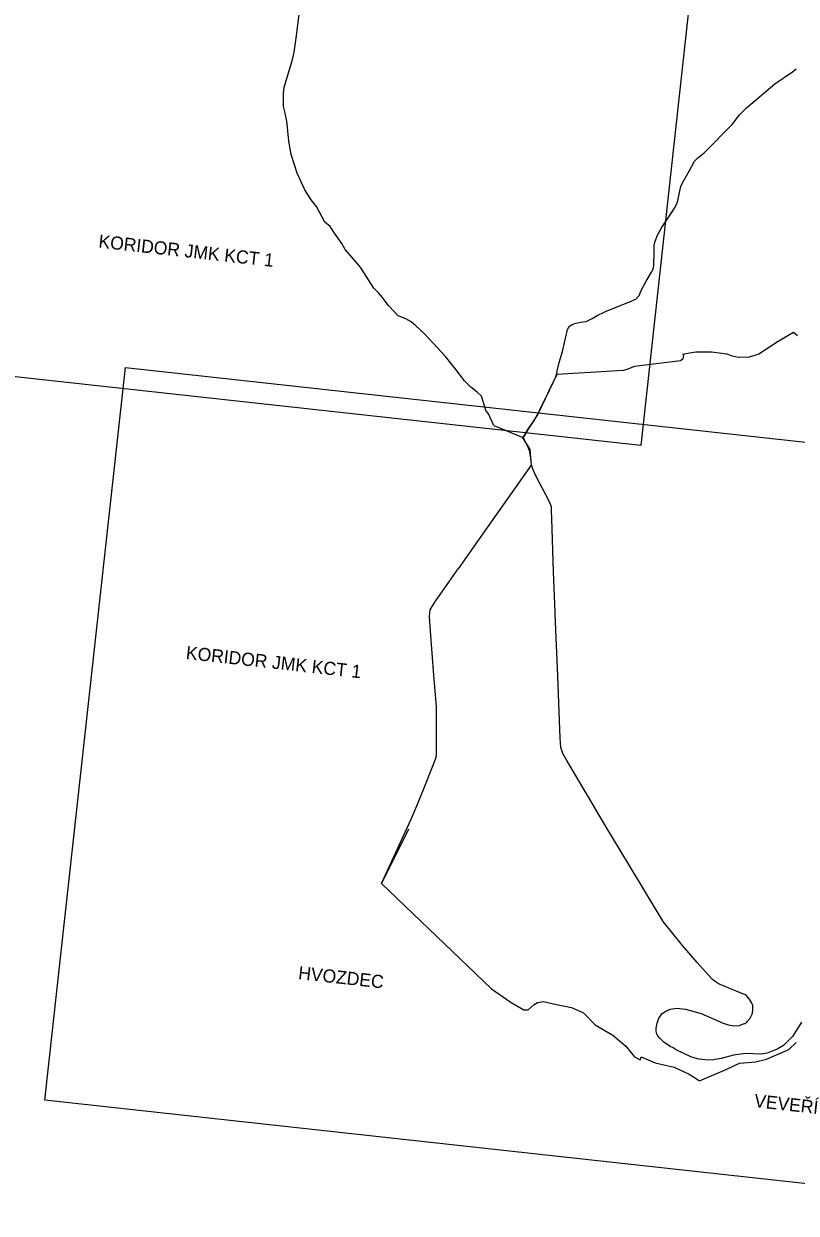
# Model space of a CAD drawing. Extents: x -678204 to -526855, y -1228851 to -1110393.
# Drawn here: x -611868 to -608331, y -1154035 to -1148586 of the extents above; entities that cross this region are included whole.
import ezdxf

# ---------------------------------------------------------------- set-up
doc = ezdxf.new("R2010")
doc.units = 0
for name, color, linetype in [('00_n_cyklo popisy detaily', 7, 'Continuous'), ('00_n_cyklo provereni rekreacni hlavni', 7, 'Continuous'), ('00_n_cyklo provereni vedlejsi', 7, 'Continuous'), ('00_n_cyklo prujezdne rekreacni hlavni', 7, 'Continuous'), ('00_n_cyklo prujezdne rekreacni vedlejsi', 7, 'Continuous'), ('00_n_cyklo trasovani rekreacni hlavni', 7, 'Continuous'), ('00_n_cyklo trasovani rekreacni vedlejsi', 7, 'Continuous'), ('_HELP', 7, 'Continuous'), ('trasy_0001', 7, 'Continuous')]:
    doc.layers.add(name, color=color, linetype=linetype)

msp = doc.modelspace()

# ---------------------------------------------------------------- linework, layer by layer
at = {"layer": '00_n_cyklo provereni rekreacni hlavni'}
msp.add_lwpolyline([(-610229.4, -1152524.2), (-609726.1, -1153007), (-609635.8, -1153070.5), (-609578.3, -1153104.1), (-609558.5, -1153103), (-609530.7, -1153078.7), (-609515.6, -1153070.6), (-609488.7, -1153064.8), (-609429.1, -1153079), (-609360.6, -1153092), (-609305.4, -1153116.6), (-609251.3, -1153171.7), (-609170.1, -1153218.9), (-609111.3, -1153270.2), (-609071.8, -1153318.3), (-609046.1, -1153333.1), (-609041.3, -1153319.5), (-608976.5, -1153346.2), (-608890.1, -1153365.6), (-608821.5, -1153398.3), (-608797, -1153414.1), (-608774.6, -1153428.6), (-608648.6, -1153375.7), (-608590.9, -1153348.1), (-608517, -1153342), (-608466.4, -1153329), (-608364.2, -1153284.5), (-608331.3, -1153253.1)], dxfattribs=at)
at = {"layer": '00_n_cyklo provereni vedlejsi'}
msp.add_lwpolyline([(-608324.7, -1150015.4), (-608342.7, -1150000.3), (-608413.9, -1150041.7), (-608502.3, -1150099.8), (-608546.4, -1150113.5), (-608594.6, -1150114.8), (-608622.3, -1150108.5), (-608648.7, -1150100.1), (-608718.2, -1150091.1), (-608790.3, -1150090.8), (-608835.9, -1150097.8), (-608851.5, -1150100.5)], dxfattribs=at)
at = {"layer": '00_n_cyklo prujezdne rekreacni hlavni'}
for points in [[(-609716.2, -1150426.9), (-609740.5, -1150373.6), (-609751.7, -1150358.4), (-609762.3, -1150321.4), (-609772, -1150291.4), (-609792.3, -1150273.7), (-609820.9, -1150250.8), (-609849.9, -1150221.8), (-609894.4, -1150164.2), (-609936.9, -1150111), (-609972, -1150072.7), (-610034.8, -1150005), (-610073.4, -1149969.9), (-610095, -1149951.5), (-610119.1, -1149937.4), (-610154.3, -1149924.8), (-610198.1, -1149876.8), (-610226.4, -1149838.5), (-610242.5, -1149820.7), (-610265, -1149796.6), (-610324.3, -1149704.4), (-610333.6, -1149691.6), (-610396.1, -1149620.4), (-610411.6, -1149592.7), (-610445.4, -1149545.9), (-610464.7, -1149514.1), (-610489.2, -1149494.7), (-610528.5, -1149422.9), (-610551.7, -1149393.2), (-610580.6, -1149347.2), (-610616.1, -1149270.8), (-610644.4, -1149184.8), (-610654.4, -1149124.3), (-610658.3, -1149076.6), (-610663.1, -1149032.4), (-610670.8, -1148995.1), (-610678.2, -1148965.1), (-610679.2, -1148904.9), (-610675.3, -1148877.2), (-610639.2, -1148755.4), (-610629.6, -1148715.8), (-610619.9, -1148642), (-610607.7, -1148541.5)], [(-609716.2, -1150426.9), (-609585.2, -1150479.7), (-609551.1, -1150537), (-609544.8, -1150608.8), (-609728.4, -1150867.5), (-609878.9, -1151083.4)], [(-610229.4, -1152524.2), (-610094.5, -1152230.5), (-610064.4, -1152158.2), (-610026.3, -1152063), (-609980.5, -1151947.7), (-609977.7, -1151927.6), (-609978.1, -1151748.4), (-609978.5, -1151715), (-609990.5, -1151570.4), (-610006.2, -1151368.3), (-610010.2, -1151300.8), (-610006.6, -1151270.6), (-609986.5, -1151236.5), (-609878.9, -1151083.4)], [(-610106.5, -1152276.3), (-610229.4, -1152524.2)]]:
    msp.add_lwpolyline(points, dxfattribs=at)
at = {"layer": '00_n_cyklo prujezdne rekreacni vedlejsi'}
msp.add_lwpolyline([(-608847.3, -1150101.4), (-608849.6, -1150121.9), (-608860.2, -1150129.5), (-609070.9, -1150156.6), (-609106.2, -1150170.3), (-609121.9, -1150174), (-609426.8, -1150193), (-609516, -1150378.2), (-609556.3, -1150440.5), (-609581.7, -1150482)], dxfattribs=at)
at = {"layer": '00_n_cyklo trasovani rekreacni hlavni'}
for points in [[(-609716.2, -1150426.9), (-609740.5, -1150373.6), (-609751.7, -1150358.4), (-609762.3, -1150321.4), (-609772, -1150291.4), (-609792.3, -1150273.7), (-609820.9, -1150250.8), (-609849.9, -1150221.8), (-609894.4, -1150164.2), (-609936.9, -1150111), (-609972, -1150072.7), (-610034.8, -1150005), (-610073.4, -1149969.9), (-610095, -1149951.5), (-610119.1, -1149937.4), (-610154.3, -1149924.8), (-610198.1, -1149876.8), (-610226.4, -1149838.5), (-610242.5, -1149820.7), (-610265, -1149796.6), (-610324.3, -1149704.4), (-610333.6, -1149691.6), (-610396.1, -1149620.4), (-610411.6, -1149592.7), (-610445.4, -1149545.9), (-610464.7, -1149514.1), (-610489.2, -1149494.7), (-610528.5, -1149422.9), (-610551.7, -1149393.2), (-610580.6, -1149347.2), (-610616.1, -1149270.8), (-610644.4, -1149184.8), (-610654.4, -1149124.3), (-610658.3, -1149076.6), (-610663.1, -1149032.4), (-610670.8, -1148995.1), (-610678.2, -1148965.1), (-610679.2, -1148904.9), (-610675.3, -1148877.2), (-610639.2, -1148755.4), (-610629.6, -1148715.8), (-610619.9, -1148642), (-610607.7, -1148541.5)], [(-609716.2, -1150426.9), (-609585.2, -1150479.7), (-609551.1, -1150537), (-609544.8, -1150608.8), (-609728.4, -1150867.5), (-609878.9, -1151083.4)], [(-610229.4, -1152524.2), (-610094.5, -1152230.5), (-610064.4, -1152158.2), (-610026.3, -1152063), (-609980.5, -1151947.7), (-609977.7, -1151927.6), (-609978.1, -1151748.4), (-609978.5, -1151715), (-609990.5, -1151570.4), (-610006.2, -1151368.3), (-610010.2, -1151300.8), (-610006.6, -1151270.6), (-609986.5, -1151236.5), (-609878.9, -1151083.4)], [(-610106.5, -1152276.3), (-610229.4, -1152524.2)], [(-610229.4, -1152524.2), (-609726.1, -1153007), (-609635.8, -1153070.5), (-609578.3, -1153104.1), (-609558.5, -1153103), (-609530.7, -1153078.7), (-609515.6, -1153070.6), (-609488.7, -1153064.8), (-609429.1, -1153079), (-609360.6, -1153092), (-609305.4, -1153116.6), (-609251.3, -1153171.7), (-609170.1, -1153218.9), (-609111.3, -1153270.2), (-609071.8, -1153318.3), (-609046.1, -1153333.1), (-609041.3, -1153319.5), (-608976.5, -1153346.2), (-608890.1, -1153365.6), (-608821.5, -1153398.3), (-608797, -1153414.1), (-608774.6, -1153428.6), (-608648.6, -1153375.7), (-608590.9, -1153348.1), (-608517, -1153342), (-608466.4, -1153329), (-608364.2, -1153284.5), (-608331.3, -1153253.1)]]:
    msp.add_lwpolyline(points, dxfattribs=at)
at = {"layer": '00_n_cyklo trasovani rekreacni vedlejsi'}
for points in [[(-608324.7, -1150015.4), (-608342.7, -1150000.3), (-608413.9, -1150041.7), (-608502.3, -1150099.8), (-608546.4, -1150113.5), (-608594.6, -1150114.8), (-608622.3, -1150108.5), (-608648.7, -1150100.1), (-608718.2, -1150091.1), (-608790.3, -1150090.8), (-608835.9, -1150097.8), (-608851.5, -1150100.5)], [(-608847.3, -1150101.4), (-608849.6, -1150121.9), (-608860.2, -1150129.5), (-609070.9, -1150156.6), (-609106.2, -1150170.3), (-609121.9, -1150174), (-609426.8, -1150193), (-609516, -1150378.2), (-609556.3, -1150440.5), (-609581.7, -1150482)]]:
    msp.add_lwpolyline(points, dxfattribs=at)
at = {"layer": '_HELP'}
for points in [[(-613388.8, -1146642.2), (-608674.3, -1147159.9), (-609043, -1150517.4), (-613757.5, -1149999.7)], [(-611402.9, -1150160), (-606688.3, -1150677.7), (-607057, -1154035.2), (-611771.6, -1153517.5)]]:
    msp.add_lwpolyline(points, close=True, dxfattribs=at)
at = {"layer": 'trasy_0001'}
msp.add_lwpolyline([(-608307, -1153160.2), (-608348.4, -1153225.9), (-608388.7, -1153267.4), (-608418.9, -1153283), (-608464.2, -1153302.5), (-608488.2, -1153306.6), (-608529.8, -1153304.4), (-608547.5, -1153302.9), (-608573.9, -1153304.8), (-608617.9, -1153311.7), (-608674.1, -1153326.2), (-608702.7, -1153331.2), (-608715.8, -1153333.5), (-608748, -1153333), (-608774.8, -1153328.8), (-608783.2, -1153327.5), (-608813.8, -1153319.2), (-608880.9, -1153286.7), (-608894.1, -1153278.2), (-608907.5, -1153271.4), (-608937.4, -1153251.1), (-608955.9, -1153233.9), (-608965.9, -1153220.8), (-608970.2, -1153209.3), (-608972.4, -1153200.1), (-608972, -1153187.5), (-608968.3, -1153164.8), (-608959.5, -1153141.7), (-608944.3, -1153119.9), (-608924.9, -1153108.3), (-608907.2, -1153100), (-608879, -1153095.8), (-608837.3, -1153100.9), (-608766.5, -1153120.9), (-608665.7, -1153164.5), (-608640.5, -1153172.7), (-608616.9, -1153177.3), (-608591.6, -1153175), (-608572.5, -1153167.3), (-608567, -1153165.5), (-608557.6, -1153159.4), (-608553.7, -1153155.8), (-608542.2, -1153141.4), (-608538.2, -1153135.5), (-608533.4, -1153123.8), (-608531.7, -1153117), (-608530, -1153103.3), (-608529.6, -1153085.4), (-608529.6, -1153083.4), (-608536, -1153070.6), (-608540.1, -1153062.3), (-608545.5, -1153054.1), (-608562, -1153035.4), (-608579.5, -1153028.2), (-608601.8, -1153019.1), (-608638.8, -1153003.9), (-608658.8, -1152995.7), (-608683.1, -1152985.6), (-608702.1, -1152973.1), (-608714.4, -1152963.9), (-608732.1, -1152944.5), (-608772.1, -1152900.6), (-608784.7, -1152886.8), (-608851.2, -1152809.2), (-608940.6, -1152699), (-609097.5, -1152437), (-609202.5, -1152263.4), (-609263.3, -1152160.1), (-609381.3, -1151961.6), (-609399.4, -1151929.2), (-609408.7, -1151901.3), (-609411.9, -1151859.1), (-609422.4, -1151574.1), (-609434.5, -1151291.3), (-609435.1, -1151282.5), (-609441.1, -1151133.1), (-609442, -1151095.6), (-609450.1, -1150853.2), (-609451, -1150819.4), (-609451.5, -1150799.2), (-609460.3, -1150775.7), (-609524.9, -1150653.3), (-609538.7, -1150621.9), (-609543.4, -1150606.2), (-609546.6, -1150577.5), (-609550.4, -1150547.8), (-609556.8, -1150530.7), (-609565.1, -1150513.6), (-609581.7, -1150482), (-609556.3, -1150440.5), (-609532.4, -1150406.8), (-609516, -1150378.2), (-609499, -1150340.3), (-609467.6, -1150276.1), (-609464, -1150269.2), (-609432.6, -1150206.8), (-609428.4, -1150195), (-609425.1, -1150177.4), (-609416, -1150137.9), (-609400.8, -1150087.4), (-609378.2, -1149987.3), (-609370.3, -1149973.6), (-609357.5, -1149963.6), (-609340.3, -1149957.5), (-609308.5, -1149951.7), (-609292.2, -1149949.6), (-609289.1, -1149948.6), (-609264.7, -1149936.4), (-609242.7, -1149923.1), (-609204.6, -1149904), (-609102.2, -1149863.5), (-609089.2, -1149858.8), (-609063.6, -1149846.4), (-609049.8, -1149830.2), (-609041.1, -1149807.4), (-609017.8, -1149764.6), (-608993, -1149724.4), (-608985.5, -1149709.7), (-608982.3, -1149693.1), (-608982, -1149634), (-608980.7, -1149602.1), (-608978.1, -1149587.3), (-608965.9, -1149554), (-608947.9, -1149521.6), (-608944.3, -1149516.2), (-608938.7, -1149507.6), (-608898.8, -1149447), (-608888.5, -1149431.2), (-608885.6, -1149426.9), (-608877.8, -1149409.4), (-608876.4, -1149406.3), (-608871.5, -1149389.6), (-608864.3, -1149350.8), (-608860.1, -1149332.2), (-608851.2, -1149314), (-608819.3, -1149257.6), (-608796.7, -1149216.1), (-608783, -1149201.9), (-608753.1, -1149177.8), (-608623.8, -1149047.1), (-608590.1, -1149003.6), (-608558.2, -1148970.6), (-608428.4, -1148861.5), (-608348.4, -1148806.2), (-608330.9, -1148793)], dxfattribs=at)

# ---------------------------------------------------------------- texts
at = {"layer": '00_n_cyklo popisy detaily'}
for s, p in [('KORIDOR JMK KCT 1', (-611528.3, -1149611.2)), ('KORIDOR JMK KCT 1', (-611128, -1151496)), ('HVOZDEC', (-610613.5, -1152962.5)), ('VEVEŘÍ', (-608525.7, -1153548.6))]:
    msp.add_text(s, height=60, rotation=353.6836, dxfattribs=at).set_placement(p)

doc.saveas('drawing.dxf')
